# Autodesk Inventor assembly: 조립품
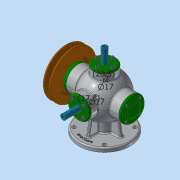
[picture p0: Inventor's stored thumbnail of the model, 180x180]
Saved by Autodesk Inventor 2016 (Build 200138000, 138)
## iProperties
Created: 2019-11
Part Number: 조립품
Material: 일반
Document SubType Name: Assembly
Designer: user
Mass: 3778.23 g
Surface Area: 2410.88 cm^2
Volume: 904.616 cm^3
Density: 4.17662 g/cm^3
Author: user
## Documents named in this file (17)
- C:\Users\user\Desktop\391120V1003\조립품.iam
- C:\Users\user\Desktop\391120V1003\V-벨트풀리.ipt
- C:\Users\user\Desktop\391120V1003\너트 M8x1.ipt
- C:\Users\user\Desktop\391120V1003\뒤커버.ipt
- C:\Users\user\Desktop\391120V1003\베어링 6202.ipt
- C:\Users\user\Desktop\391120V1003\본체.ipt
- C:\Users\user\Desktop\391120V1003\본체커버.ipt
- C:\Users\user\Desktop\391120V1003\볼트 M4.ipt
- C:\Users\user\Desktop\391120V1003\스프링1.ipt
- C:\Users\user\Desktop\391120V1003\스프링2.ipt
- C:\Users\user\Desktop\391120V1003\슬라이드 커버.ipt
- C:\Users\user\Desktop\391120V1003\슬라이드.ipt
- C:\Users\user\Desktop\391120V1003\앞커버.ipt
- C:\Users\user\Desktop\391120V1003\오일 실.ipt
- C:\Users\user\Desktop\391120V1003\와셔 8x17.ipt
- C:\Users\user\Desktop\391120V1003\축.ipt
- C:\Users\user\Desktop\391120V1003\키 4x4.ipt
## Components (1 placed, 1 different names)
1. V-벨트풀리:1
